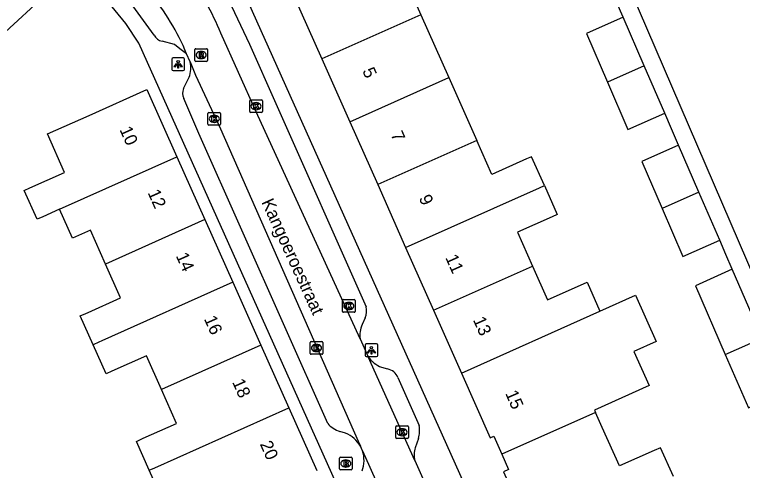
# Model space of a CAD drawing. Extents: x 163150 to 163546, y 380933 to 381635.
# Drawn here: x 163251.7 to 163309.2, y 381187.2 to 381223.2 of the extents above; entities that cross this region are included whole.
import ezdxf

# ---------------------------------------------------------------- set-up
doc = ezdxf.new("R2010")
doc.units = 0
for name, color, linetype in [('IMGEO_Brandkraan', 7, 'Continuous'), ('IMGEO_Kolk', 7, 'Continuous'), ('IMGEO_Lichtpunt', 7, 'Continuous'), ('IMGEO_Openbare_ruimte_label', 7, 'Continuous'), ('IMGEO_Pand', 7, 'Continuous'), ('IMGEO_Pand_nummerreeks', 7, 'Continuous'), ('IMGEO_Rijbaan_lokaal_open', 7, 'Continuous'), ('IMGEO_Rioolput', 7, 'Continuous'), ('IMGEO_Voetpad_open', 7, 'Continuous')]:
    doc.layers.add(name, color=color, linetype=linetype)

msp = doc.modelspace()

# ---------------------------------------------------------------- linework, layer by layer
at = {"layer": 'IMGEO_Brandkraan'}
for p, q in [((163277.371, 381187.358), (163277.371, 381188.21)), ((163277.446, 381188.284), (163278.298, 381188.284)), ((163278.372, 381188.21), (163278.372, 381187.358)), ((163277.859, 381188.064), (163277.884, 381188.064)), ((163278.298, 381187.284), (163277.446, 381187.284)), ((163277.882, 381187.504), (163277.857, 381187.504))]:
    msp.add_line(p, q, dxfattribs=at)
for points in [[(163277.371, 381187.358), (163277.371, 381188.21)], [(163277.446, 381188.284), (163278.298, 381188.284)], [(163278.372, 381188.21), (163278.372, 381187.358)], [(163277.719, 381187.984), (163277.719, 381187.584), (163277.932, 381187.584)], [(163277.95, 381187.984), (163277.719, 381187.984)], [(163277.898, 381187.903), (163277.844, 381187.903), (163277.844, 381187.827)], [(163277.844, 381187.827), (163277.897, 381187.827)], [(163277.906, 381187.751), (163277.844, 381187.751), (163277.844, 381187.67)], [(163277.844, 381187.67), (163277.906, 381187.67)], [(163278.298, 381187.284), (163277.446, 381187.284)]]:
    msp.add_lwpolyline(points, dxfattribs=at)
for centre, radius, start, end in [((163277.448, 381188.208), 0.0765, 91.55205, 178.44795), ((163277.448, 381188.208), 0.0765, 91.55205, 178.44795), ((163278.296, 381188.208), 0.0765, 1.55205, 88.44795), ((163278.296, 381188.208), 0.0765, 1.55205, 88.44795), ((163277.899, 381187.865), 0.0379, 267.82845, 90.93552), ((163277.907, 381187.71), 0.0404, 269.87594, 90.50774), ((163277.938, 381187.835), 0.251, 268.66757, 293.53466), ((163277.954, 381187.839), 0.145, 59.4692, 91.53667), ((163277.979, 381187.886), 0.0922, 285.51372, 58.15012), ((163277.984, 381187.694), 0.105, 301.31148, 78.98903), ((163277.448, 381187.36), 0.0765, 181.55205, 268.44795), ((163277.448, 381187.36), 0.0765, 181.55205, 268.44795), ((163278.296, 381187.36), 0.0765, 271.55205, 358.44795), ((163278.296, 381187.36), 0.0765, 271.55205, 358.44795)]:
    msp.add_arc(centre, radius, start, end, dxfattribs=at)
for centre, major_axis, ratio, start_param, end_param in [((163277.858, 381187.784), (-0.387, 0.002), 0.722429, 4.712389, 7.853982), ((163277.883, 381187.784), (-0.39, 0.002), 0.717154, 1.570796, 4.712389)]:
    msp.add_ellipse(centre, major_axis=major_axis, ratio=ratio, start_param=start_param, end_param=end_param, dxfattribs=at)
at = {"layer": 'IMGEO_Kolk'}
for p, q in [((163270.279, 381215.549), (163270.279, 381216.401)), ((163270.354, 381216.475), (163271.206, 381216.475)), ((163271.28, 381216.401), (163271.28, 381215.549)), ((163270.767, 381216.255), (163270.792, 381216.255)), ((163266.982, 381214.554), (163266.982, 381215.406)), ((163267.057, 381215.48), (163267.909, 381215.48)), ((163267.47, 381215.26), (163267.495, 381215.26)), ((163267.983, 381215.406), (163267.983, 381214.554)), ((163271.206, 381215.475), (163270.354, 381215.475)), ((163270.79, 381215.695), (163270.765, 381215.695)), ((163267.493, 381214.7), (163267.468, 381214.7)), ((163267.909, 381214.48), (163267.057, 381214.48)), ((163277.613, 381199.788), (163277.613, 381200.64)), ((163277.688, 381200.714), (163278.54, 381200.714)), ((163278.101, 381200.494), (163278.126, 381200.494)), ((163278.614, 381200.64), (163278.614, 381199.788)), ((163278.54, 381199.714), (163277.688, 381199.714)), ((163278.124, 381199.934), (163278.099, 381199.934)), ((163275.125, 381197.397), (163275.977, 381197.397)), ((163275.05, 381196.471), (163275.05, 381197.323)), ((163275.538, 381197.177), (163275.563, 381197.177)), ((163276.051, 381197.323), (163276.051, 381196.471)), ((163275.977, 381196.397), (163275.125, 381196.397)), ((163275.561, 381196.617), (163275.536, 381196.617)), ((163281.81, 381189.824), (163281.81, 381190.676)), ((163281.885, 381190.75), (163282.737, 381190.75)), ((163282.298, 381190.53), (163282.323, 381190.53)), ((163282.811, 381190.676), (163282.811, 381189.824)), ((163282.321, 381189.97), (163282.296, 381189.97)), ((163282.737, 381189.75), (163281.885, 381189.75))]:
    msp.add_line(p, q, dxfattribs=at)
for points in [[(163270.279, 381215.549), (163270.279, 381216.401)], [(163270.354, 381216.475), (163271.206, 381216.475)], [(163271.28, 381216.401), (163271.28, 381215.549)], [(163270.6, 381216.175), (163270.723, 381216.175), (163270.723, 381216.024), (163270.853, 381216.175), (163271.017, 381216.175), (163270.871, 381216.024), (163271.024, 381215.775), (163270.872, 381215.775), (163270.787, 381215.939), (163270.723, 381215.872), (163270.723, 381215.775), (163270.6, 381215.775), (163270.6, 381216.175)], [(163266.982, 381214.554), (163266.982, 381215.406)], [(163267.057, 381215.48), (163267.909, 381215.48)], [(163267.303, 381215.18), (163267.426, 381215.18), (163267.426, 381215.029), (163267.556, 381215.18), (163267.72, 381215.18), (163267.574, 381215.029), (163267.727, 381214.78), (163267.575, 381214.78), (163267.49, 381214.944), (163267.426, 381214.877), (163267.426, 381214.78), (163267.303, 381214.78), (163267.303, 381215.18)], [(163267.983, 381215.406), (163267.983, 381214.554)], [(163271.206, 381215.475), (163270.354, 381215.475)], [(163267.909, 381214.48), (163267.057, 381214.48)], [(163277.613, 381199.788), (163277.613, 381200.64)], [(163277.688, 381200.714), (163278.54, 381200.714)], [(163277.934, 381200.414), (163278.057, 381200.414), (163278.057, 381200.263), (163278.187, 381200.414), (163278.351, 381200.414), (163278.205, 381200.263), (163278.358, 381200.014), (163278.206, 381200.014), (163278.121, 381200.178), (163278.057, 381200.111), (163278.057, 381200.014), (163277.934, 381200.014), (163277.934, 381200.414)], [(163278.614, 381200.64), (163278.614, 381199.788)], [(163278.54, 381199.714), (163277.688, 381199.714)], [(163275.125, 381197.397), (163275.977, 381197.397)], [(163275.05, 381196.471), (163275.05, 381197.323)], [(163275.371, 381197.097), (163275.494, 381197.097), (163275.494, 381196.946), (163275.624, 381197.097), (163275.788, 381197.097), (163275.642, 381196.946), (163275.795, 381196.697), (163275.643, 381196.697), (163275.558, 381196.861), (163275.494, 381196.794), (163275.494, 381196.697), (163275.371, 381196.697), (163275.371, 381197.097)], [(163276.051, 381197.323), (163276.051, 381196.471)], [(163275.977, 381196.397), (163275.125, 381196.397)], [(163281.81, 381189.824), (163281.81, 381190.676)], [(163281.885, 381190.75), (163282.737, 381190.75)], [(163282.131, 381190.45), (163282.254, 381190.45), (163282.254, 381190.299), (163282.384, 381190.45), (163282.548, 381190.45), (163282.402, 381190.299), (163282.555, 381190.05), (163282.403, 381190.05), (163282.318, 381190.214), (163282.254, 381190.147), (163282.254, 381190.05), (163282.131, 381190.05), (163282.131, 381190.45)], [(163282.811, 381190.676), (163282.811, 381189.824)], [(163282.737, 381189.75), (163281.885, 381189.75)]]:
    msp.add_lwpolyline(points, dxfattribs=at)
for centre, start, end in [((163270.356, 381216.399), 91.55205, 178.44795), ((163270.356, 381216.399), 91.55205, 178.44795), ((163271.204, 381216.399), 1.55205, 88.44795), ((163271.204, 381216.399), 1.55205, 88.44795), ((163267.059, 381215.404), 91.55205, 178.44795), ((163267.059, 381215.404), 91.55205, 178.44795), ((163267.907, 381215.404), 1.55205, 88.44795), ((163267.907, 381215.404), 1.55205, 88.44795), ((163270.356, 381215.551), 181.55205, 268.44795), ((163270.356, 381215.551), 181.55205, 268.44795), ((163271.204, 381215.551), 271.55205, 358.44795), ((163271.204, 381215.551), 271.55205, 358.44795), ((163267.059, 381214.556), 181.55205, 268.44795), ((163267.059, 381214.556), 181.55205, 268.44795), ((163267.907, 381214.556), 271.55205, 358.44795), ((163267.907, 381214.556), 271.55205, 358.44795), ((163277.69, 381200.638), 91.55205, 178.44795), ((163277.69, 381200.638), 91.55205, 178.44795), ((163278.538, 381200.638), 1.55205, 88.44795), ((163278.538, 381200.638), 1.55205, 88.44795), ((163277.69, 381199.79), 181.55205, 268.44795), ((163277.69, 381199.79), 181.55205, 268.44795), ((163278.538, 381199.79), 271.55205, 358.44795), ((163278.538, 381199.79), 271.55205, 358.44795), ((163275.127, 381197.321), 91.55205, 178.44795), ((163275.127, 381197.321), 91.55205, 178.44795), ((163275.975, 381197.321), 1.55205, 88.44795), ((163275.975, 381197.321), 1.55205, 88.44795), ((163275.127, 381196.473), 181.55205, 268.44795), ((163275.127, 381196.473), 181.55205, 268.44795), ((163275.975, 381196.473), 271.55205, 358.44795), ((163275.975, 381196.473), 271.55205, 358.44795), ((163281.887, 381190.674), 91.55205, 178.44795), ((163281.887, 381190.674), 91.55205, 178.44795), ((163282.735, 381190.674), 1.55205, 88.44795), ((163282.735, 381190.674), 1.55205, 88.44795), ((163281.887, 381189.826), 181.55205, 268.44795), ((163281.887, 381189.826), 181.55205, 268.44795), ((163282.735, 381189.826), 271.55205, 358.44795), ((163282.735, 381189.826), 271.55205, 358.44795)]:
    msp.add_arc(centre, 0.0765, start, end, dxfattribs=at)
for centre, major_axis, ratio, start_param, end_param in [((163270.766, 381215.975), (-0.387, 0.002), 0.722429, 4.712389, 7.853982), ((163270.791, 381215.975), (-0.39, 0.002), 0.717154, 1.570796, 4.712389), ((163267.469, 381214.98), (-0.387, 0.002), 0.722429, 4.712389, 7.853982), ((163267.494, 381214.98), (-0.39, 0.002), 0.717154, 1.570796, 4.712389), ((163278.1, 381200.214), (-0.387, 0.002), 0.722429, 4.712389, 7.853982), ((163278.125, 381200.214), (-0.39, 0.002), 0.717154, 1.570796, 4.712389), ((163275.537, 381196.897), (-0.387, 0.002), 0.722429, 4.712389, 7.853982), ((163275.562, 381196.897), (-0.39, 0.002), 0.717154, 1.570796, 4.712389), ((163282.297, 381190.25), (-0.387, 0.002), 0.722429, 4.712389, 7.853982), ((163282.322, 381190.25), (-0.39, 0.002), 0.717154, 1.570796, 4.712389)]:
    msp.add_ellipse(centre, major_axis=major_axis, ratio=ratio, start_param=start_param, end_param=end_param, dxfattribs=at)
at = {"layer": 'IMGEO_Lichtpunt'}
for p, q in [((163265.038, 381219.781), (163264.23, 381219.781)), ((163265.038, 381219.781), (163264.23, 381219.781)), ((163264.136, 381219.686), (163264.136, 381218.879)), ((163264.136, 381219.686), (163264.136, 381218.879)), ((163265.132, 381218.879), (163265.132, 381219.686)), ((163265.132, 381218.879), (163265.132, 381219.686)), ((163264.23, 381218.785), (163265.038, 381218.785)), ((163264.23, 381218.785), (163265.038, 381218.785)), ((163279.391, 381197.12), (163279.391, 381196.313)), ((163279.391, 381197.12), (163279.391, 381196.313)), ((163280.293, 381197.215), (163279.485, 381197.215)), ((163280.293, 381197.215), (163279.485, 381197.215)), ((163280.387, 381196.313), (163280.387, 381197.12)), ((163280.387, 381196.313), (163280.387, 381197.12)), ((163279.485, 381196.219), (163280.293, 381196.219)), ((163279.485, 381196.219), (163280.293, 381196.219))]:
    msp.add_line(p, q, dxfattribs=at)
for points in [[(163264.51, 381219.35), (163264.549, 381219.322), (163264.361, 381219.06), (163264.323, 381219.087), (163264.51, 381219.35)], [(163264.612, 381219.302), (163264.659, 381219.302), (163264.659, 381218.98), (163264.612, 381218.98), (163264.612, 381219.302)], [(163264.722, 381219.322), (163264.76, 381219.349), (163264.947, 381219.087), (163264.908, 381219.059), (163264.722, 381219.322)], [(163279.765, 381196.784), (163279.804, 381196.756), (163279.616, 381196.494), (163279.578, 381196.521), (163279.765, 381196.784)], [(163279.977, 381196.756), (163280.015, 381196.783), (163280.202, 381196.521), (163280.163, 381196.493), (163279.977, 381196.756)], [(163279.867, 381196.736), (163279.914, 381196.736), (163279.914, 381196.414), (163279.867, 381196.414), (163279.867, 381196.736)]]:
    msp.add_lwpolyline(points, dxfattribs=at)
for centre in [(163264.635, 381219.484), (163279.89, 381196.918)]:
    msp.add_circle(centre, 0.0994, dxfattribs=at)
for centre, start, end in [((163264.23, 381219.686), 90, 180), ((163264.23, 381219.686), 90, 180), ((163265.038, 381219.686), 0, 90), ((163265.038, 381219.686), 0, 90), ((163264.23, 381218.879), 180, 270), ((163264.23, 381218.879), 180, 270), ((163265.038, 381218.879), 270, 0), ((163265.038, 381218.879), 270, 360), ((163279.485, 381197.12), 90, 180), ((163279.485, 381197.12), 90, 180), ((163280.293, 381197.12), 0, 90), ((163280.293, 381197.12), 0, 90), ((163279.485, 381196.313), 180, 270), ((163279.485, 381196.313), 180, 270), ((163280.293, 381196.313), 270, 0), ((163280.293, 381196.313), 270, 360)]:
    msp.add_arc(centre, 0.0946, start, end, dxfattribs=at)
at = {"layer": 'IMGEO_Pand'}
for points in [[(163250.677, 381228.873), (163254.325, 381224.911), (163250.648, 381221.524), (163247.986, 381219.073), (163245.994, 381221.236), (163243.775, 381219.218), (163243.555, 381219.018), (163241.872, 381220.867)], [(163281.602, 381228.156), (163283.805, 381223.195)], [(163273.773, 381224.674), (163275.979, 381219.714)], [(163283.805, 381223.195), (163275.979, 381219.714)], [(163283.805, 381223.195), (163286.007, 381218.234)], [(163299.776, 381222.996), (163296.867, 381221.702), (163298.53, 381217.864)], [(163301.439, 381219.158), (163299.776, 381222.996)], [(163275.979, 381219.714), (163278.184, 381214.754)], [(163301.439, 381219.158), (163298.53, 381217.864)], [(163303.052, 381215.432), (163301.439, 381219.158)], [(163278.184, 381214.754), (163286.007, 381218.234)], [(163286.007, 381218.234), (163288.21, 381213.273)], [(163298.53, 381217.864), (163300.144, 381214.137), (163303.052, 381215.432)], [(163255.259, 381207.838), (163253.944, 381207.25), (163253.499, 381207.051), (163252.479, 381209.334), (163252.924, 381209.533), (163255.664, 381210.757), (163254.311, 381213.786), (163257.6, 381215.255), (163262.165, 381217.293), (163264.536, 381211.982)], [(163278.184, 381214.754), (163280.39, 381209.794)], [(163288.21, 381213.273), (163280.39, 381209.794)], [(163293.55, 381209.708), (163292.534, 381211.992), (163292.139, 381211.816), (163289.398, 381210.597), (163288.21, 381213.273)], [(163304.15, 381212.895), (163301.242, 381211.6), (163302.844, 381207.901)], [(163305.753, 381209.195), (163304.15, 381212.895)], [(163255.259, 381207.838), (163264.536, 381211.982)], [(163264.536, 381211.982), (163266.748, 381207.029)], [(163280.39, 381209.794), (163282.595, 381204.834)], [(163282.595, 381204.834), (163293.154, 381209.532), (163293.55, 381209.708)], [(163293.55, 381209.708), (163294.566, 381207.424), (163294.169, 381207.247), (163291.427, 381206.027), (163292.616, 381203.351)], [(163305.753, 381209.195), (163302.844, 381207.901)], [(163307.393, 381205.408), (163305.753, 381209.195)], [(163258.894, 381203.521), (163257.702, 381206.191), (163256.278, 381205.555), (163255.259, 381207.838)], [(163302.844, 381207.901), (163304.487, 381204.106), (163307.393, 381205.408)], [(163266.748, 381207.029), (163258.894, 381203.521)], [(163266.748, 381207.029), (163268.958, 381202.078)], [(163282.595, 381204.834), (163284.8, 381199.874)], [(163257.925, 381197.149), (163256.904, 381199.431), (163257.347, 381199.629), (163257.526, 381199.709), (163260.086, 381200.852), (163258.894, 381203.521)], [(163284.8, 381199.874), (163292.616, 381203.351)], [(163292.616, 381203.351), (163293.795, 381200.695), (163296.92, 381202.094), (163297.934, 381199.81)], [(163308.387, 381203.113), (163305.481, 381201.811), (163307.837, 381196.372)], [(163310.746, 381197.666), (163308.387, 381203.113)], [(163268.958, 381202.078), (163258.603, 381197.452), (163258.366, 381197.346), (163257.925, 381197.149)], [(163268.958, 381202.078), (163271.17, 381197.125)], [(163297.934, 381199.81), (163300.743, 381201.067), (163302.37, 381197.403), (163300.616, 381196.616), (163301.823, 381193.924), (163297.507, 381191.987), (163297.586, 381191.811)], [(163284.8, 381199.874), (163287.005, 381194.915)], [(163287.005, 381194.915), (163297.934, 381199.81)], [(163307.837, 381196.372), (163310.746, 381197.666)], [(163263.316, 381193.617), (163262.124, 381196.287), (163259.385, 381195.063), (163258.945, 381194.866), (163257.925, 381197.149)], [(163271.17, 381197.125), (163263.316, 381193.617)], [(163271.17, 381197.125), (163273.381, 381192.174)], [(163307.837, 381196.372), (163309.657, 381192.171), (163312.566, 381193.465)], [(163287.005, 381194.915), (163289.272, 381189.817), (163289.547, 381189.939), (163290.18, 381188.516)], [(163262.35, 381187.246), (163261.33, 381189.529), (163261.769, 381189.725), (163261.872, 381189.771), (163264.508, 381190.949), (163263.316, 381193.617)], [(163262.35, 381187.246), (163262.788, 381187.442), (163273.381, 381192.174)], [(163273.381, 381192.174), (163275.592, 381187.222)], [(163297.586, 381191.811), (163290.18, 381188.516)], [(163303.738, 381186.745), (163302.722, 381189.029), (163302.222, 381188.807), (163299.481, 381187.587), (163298.121, 381190.618), (163297.586, 381191.811)], [(163290.18, 381188.516), (163290.722, 381187.298), (163290.312, 381187.114), (163292.684, 381181.828)], [(163267.738, 381183.714), (163266.546, 381186.383), (163263.807, 381185.16), (163263.37, 381184.965), (163262.35, 381187.246)]]:
    msp.add_lwpolyline(points, dxfattribs=at)
at = {"layer": 'IMGEO_Rijbaan_lokaal_open'}
for points in [[(163279.003, 381197.607), (163270.799, 381215.542), (163268.013, 381221.744)], [(163265.579, 381219.475), (163265.292, 381220.107)], [(163265.579, 381219.475), (163266, 381218.425), (163267.981, 381214.197), (163278.853, 381189.551), (163279.033, 381189.142)], [(163279.003, 381197.607), (163279.327, 381196.899), (163279.639, 381196.203)], [(163283.317, 381188.009), (163279.639, 381196.203)], [(163279.191, 381188.785), (163279.033, 381189.142)], [(163279.191, 381188.785), (163279.421, 381188.263), (163286.858, 381171.695)], [(163283.317, 381188.009), (163283.635, 381187.3), (163285.19, 381183.834), (163285.499, 381183.144)]]:
    msp.add_lwpolyline(points, dxfattribs=at)
for centre, radius, start, end in [((163245.599, 381212.256), 24.34, 22.94332, 35.50854), ((163249.024, 381213.537), 17.545, 21.99232, 40.31853)]:
    msp.add_arc(centre, radius, start, end, dxfattribs=at)
at = {"layer": 'IMGEO_Rioolput'}
for p, q in [((163265.946, 381219.589), (163265.946, 381220.441)), ((163266.021, 381220.515), (163266.873, 381220.515)), ((163266.947, 381220.441), (163266.947, 381219.589)), ((163266.434, 381220.295), (163266.459, 381220.295)), ((163266.873, 381219.515), (163266.021, 381219.515)), ((163266.457, 381219.735), (163266.432, 381219.735))]:
    msp.add_line(p, q, dxfattribs=at)
for points in [[(163265.946, 381219.589), (163265.946, 381220.441)], [(163266.021, 381220.515), (163266.873, 381220.515)], [(163266.947, 381220.441), (163266.947, 381219.589)], [(163266.535, 381220.213), (163266.283, 381220.215), (163266.283, 381219.815)], [(163266.283, 381219.815), (163266.407, 381219.815), (163266.407, 381219.977), (163266.418, 381219.977)], [(163266.461, 381220.134), (163266.407, 381220.134), (163266.407, 381220.053)], [(163266.407, 381220.053), (163266.459, 381220.053)], [(163266.465, 381219.948), (163266.536, 381219.815), (163266.676, 381219.815), (163266.611, 381219.941)], [(163266.873, 381219.515), (163266.021, 381219.515)]]:
    msp.add_lwpolyline(points, dxfattribs=at)
for centre, radius, start, end in [((163266.023, 381220.439), 0.0765, 91.55205, 178.44795), ((163266.023, 381220.439), 0.0765, 91.55205, 178.44795), ((163266.871, 381220.439), 0.0765, 1.55205, 88.44795), ((163266.871, 381220.439), 0.0765, 1.55205, 88.44795), ((163266.417, 381219.924), 0.0533, 26.02933, 88.69889), ((163266.443, 381220.242), 0.19, 274.7715, 282.96867), ((163266.467, 381220.038), 0.0964, 77.00612, 93.18647), ((163266.481, 381220.095), 0.0378, 276.66336, 79.67722), ((163266.534, 381220.103), 0.109, 350.36119, 89.41601), ((163266.532, 381220.103), 0.112, 277.58423, 350.98172), ((163266.516, 381219.888), 0.108, 29.51342, 73.79051), ((163266.023, 381219.591), 0.0765, 181.55205, 268.44795), ((163266.023, 381219.591), 0.0765, 181.55205, 268.44795), ((163266.871, 381219.591), 0.0765, 271.55205, 358.44795), ((163266.871, 381219.591), 0.0765, 271.55205, 358.44795)]:
    msp.add_arc(centre, radius, start, end, dxfattribs=at)
for centre, major_axis, ratio, start_param, end_param in [((163266.433, 381220.015), (-0.387, 0.002), 0.722429, 4.712389, 7.853982), ((163266.458, 381220.015), (-0.39, 0.002), 0.717154, 1.570796, 4.712389)]:
    msp.add_ellipse(centre, major_axis=major_axis, ratio=ratio, start_param=start_param, end_param=end_param, dxfattribs=at)
at = {"layer": 'IMGEO_Voetpad_open'}
for points in [[(163286.908, 381247.77), (163287.555, 381248.354), (163289.781, 381249.639), (163311.555, 381199.092), (163317.049, 381199.939), (163308.6, 381261.231), (163298.145, 381259.806)], [(163282.659, 381139.767), (163292.918, 381150.971), (163261.531, 381220.959), (163260.513, 381222.504), (163240.64, 381246.663)], [(163262.732, 381221.585), (163260.84, 381224.198), (163255.077, 381231.183), (163245.546, 381242.743), (163245.181, 381243.186)], [(163304.985, 381145.89), (163305.202, 381146.131), (163270.156, 381224.203), (163267.96, 381228.115)], [(163267.348, 381226.416), (163268.608, 381224.383), (163270.262, 381220.868), (163272.353, 381216.176), (163279.471, 381200.146)], [(163299.776, 381222.996), (163299.281, 381224.139), (163298.776, 381225.305)], [(163265.292, 381220.107), (163264.775, 381220.505), (163264.343, 381220.838), (163263.357, 381221.103)], [(163265.06, 381217.366), (163265.497, 381218.261)], [(163276.442, 381190.926), (163266.264, 381213.829), (163265.069, 381216.59)], [(163304.15, 381212.895), (163303.595, 381214.178), (163303.052, 381215.432)], [(163308.387, 381203.113), (163307.887, 381204.268), (163307.393, 381205.408)], [(163279.398, 381199.288), (163279.151, 381198.75)], [(163280.697, 381195.382), (163281.154, 381195.239)], [(163281.982, 381194.567), (163283.656, 381190.771)], [(163277.847, 381190.174), (163277.394, 381190.316)], [(163283.616, 381189.756), (163283.342, 381189.03)]]:
    msp.add_lwpolyline(points, dxfattribs=at)
for centre, radius, start, end in [((163263.557, 381222.009), 0.928, 207.19063, 257.53055), ((163263.688, 381218.993), 1.952, 337.97179, 14.29983), ((163265.984, 381216.989), 0.998, 157.78885, 203.54011), ((163278.184, 381199.823), 1.327, 336.20489, 14.0689), ((163281.228, 381197.9), 2.244, 157.74199, 187.50236), ((163281.432, 381197.422), 2.168, 214.19856, 250.17905), ((163280.986, 381194.186), 1.066, 20.93058, 80.94426), ((163278.054, 381192.394), 2.181, 222.32453, 252.37552), ((163281.615, 381190.343), 2.086, 343.65019, 11.83622), ((163276.989, 381187.99), 2.346, 29.39856, 68.545), ((163276.953, 381188.046), 2.357, 338.76578, 18.28556), ((163285.553, 381188.465), 2.282, 165.66631, 191.52838)]:
    msp.add_arc(centre, radius, start, end, dxfattribs=at)

# ---------------------------------------------------------------- texts
at = {"layer": 'IMGEO_Openbare_ruimte_label'}
msp.add_text('Kangoeroestraat', height=1, rotation=294.51507, dxfattribs=at).set_placement((163271.19, 381208.411))
at = {"layer": 'IMGEO_Pand_nummerreeks'}
for s, rotation, p in [('5', 293.97147, (163279.155, 381218.77)), ('10', 294.05829, (163259.984, 381214.134)), ('7', 293.97147, (163281.387, 381213.752)), ('12', 294.0607, (163262.205, 381209.159)), ('9', 293.97234, (163283.619, 381208.734)), ('14', 294.05829, (163264.43, 381204.176)), ('11', 293.97234, (163285.709, 381204.033)), ('16', 294.05829, (163266.654, 381199.195)), ('13', 293.97147, (163287.894, 381199.119)), ('18', 294.05829, (163268.879, 381194.213)), ('15', 293.45577, (163290.444, 381193.32)), ('20', 294.05829, (163271.066, 381189.315))]:
    msp.add_text(s, height=1, rotation=rotation, dxfattribs=at).set_placement(p)

doc.saveas('drawing.dxf')
